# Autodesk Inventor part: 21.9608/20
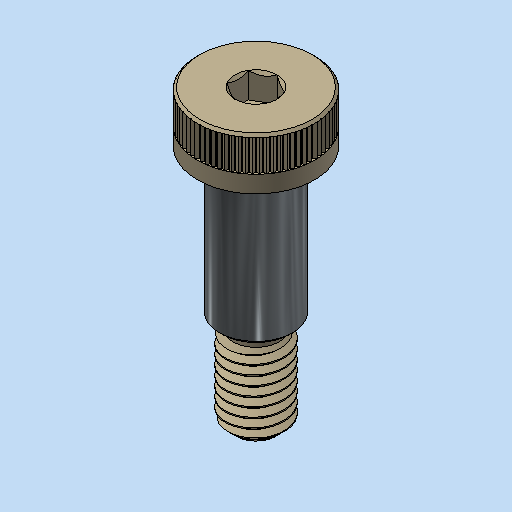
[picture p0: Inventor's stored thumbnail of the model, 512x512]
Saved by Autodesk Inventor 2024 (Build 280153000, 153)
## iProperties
Created: 2012-04
Part Number: 21.9608/20
Document SubType Name: Modeling
Designer: Administrator
Density: 7.85 g/cm^3
Material: Steel
Description: SHOULDER BOLT M8 THREAD 10mm SHLDER 20mm LONG
Vendor: V
Stock Number: MC # 92981A303
Mass: 26.3963 g
Surface Area: 19.7556 cm^2
Volume: 3.36259 cm^3
Appearance: Beige
Translation Standard: STEP AP203
FileName: 92981A303.step
PreProcessor: SolidWorks 2009
PostProcessor: Build: 236a, Release: 2009 RTM - Date: Fri 02/22/2008
Sent Units: MM
Uncertainty: 1e-05
Author: Administrator
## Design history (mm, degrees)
feature "Base1"
body "Solid1"
